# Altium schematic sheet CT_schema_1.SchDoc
size 471 x 471 mm
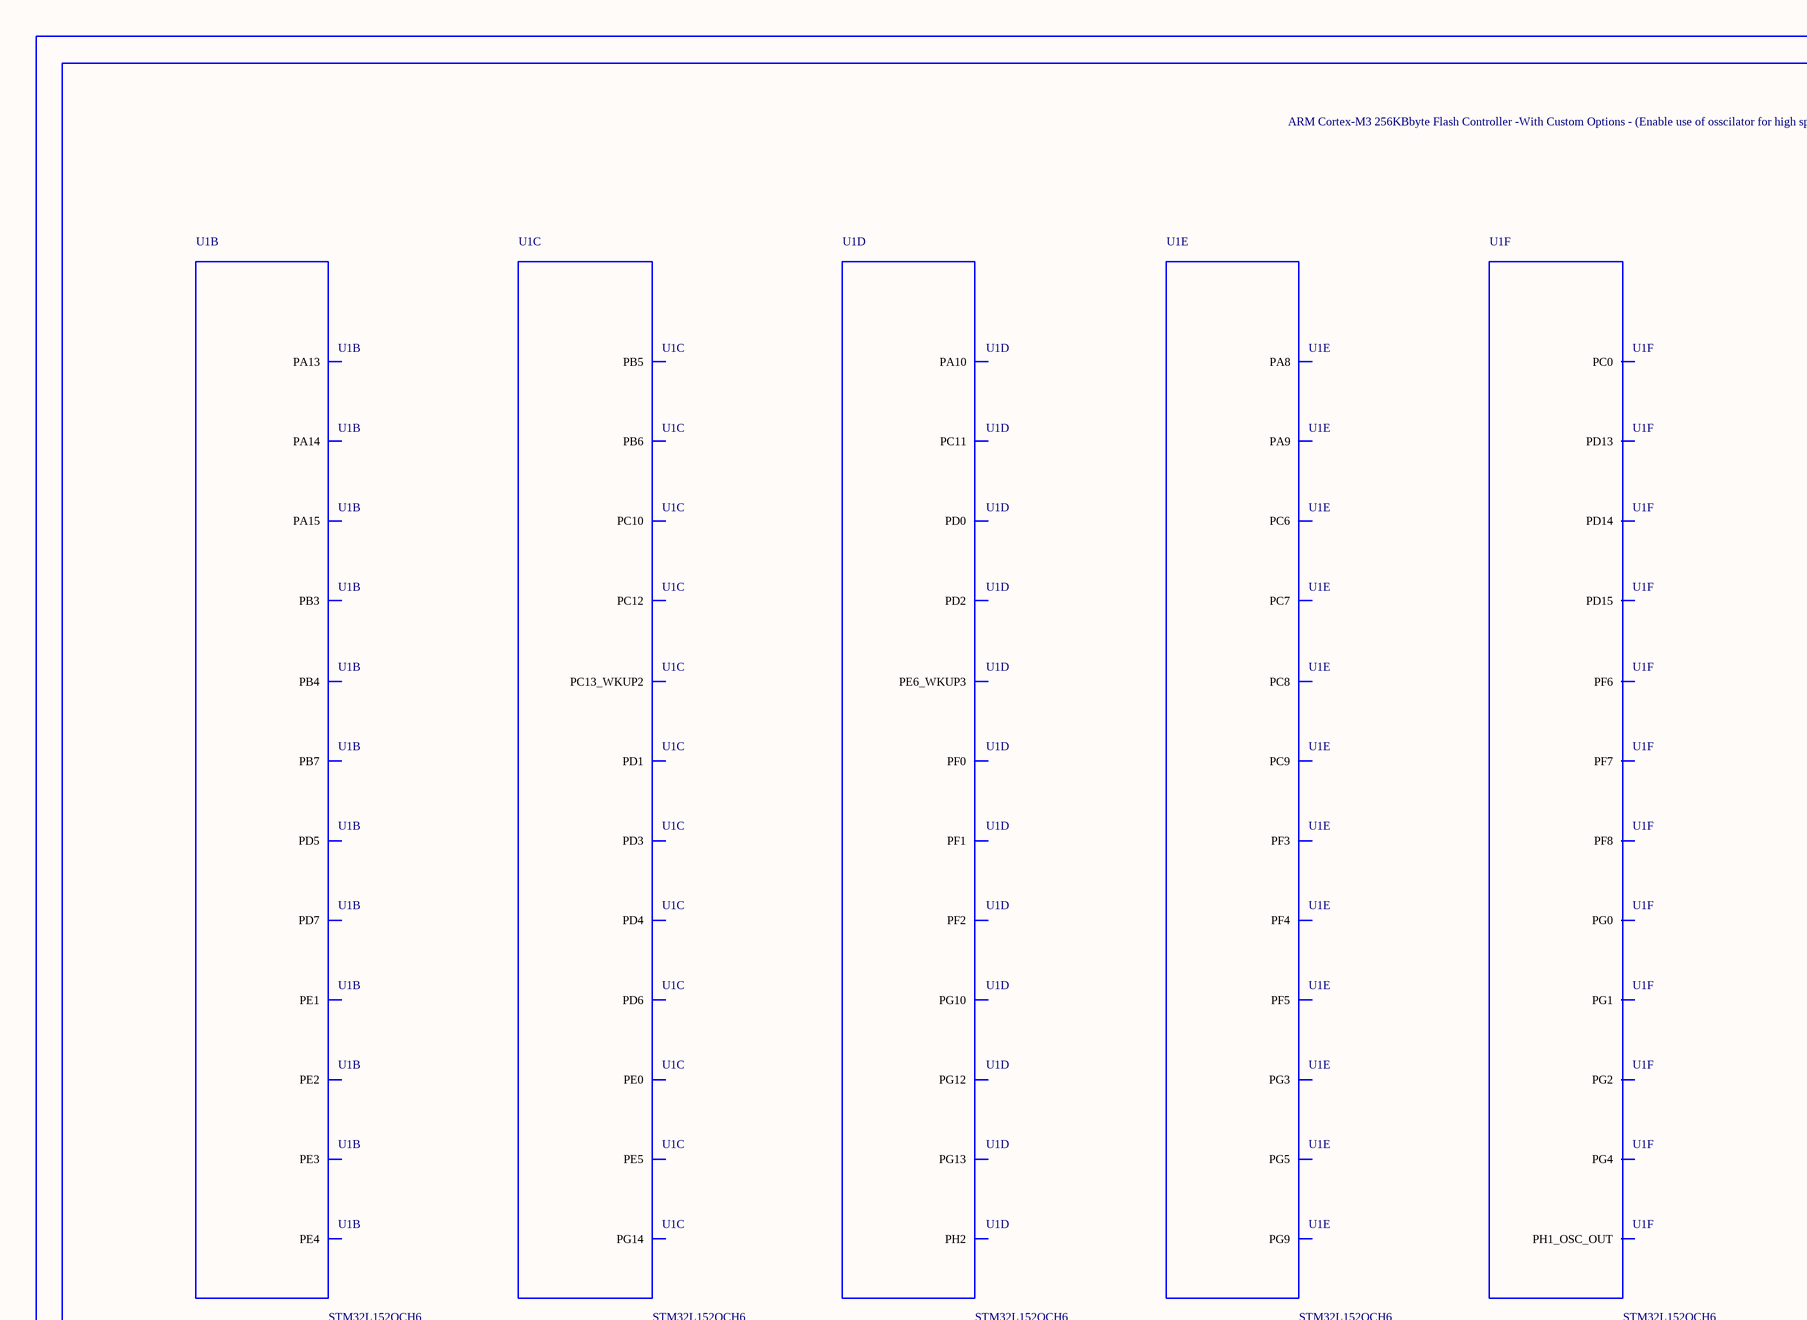
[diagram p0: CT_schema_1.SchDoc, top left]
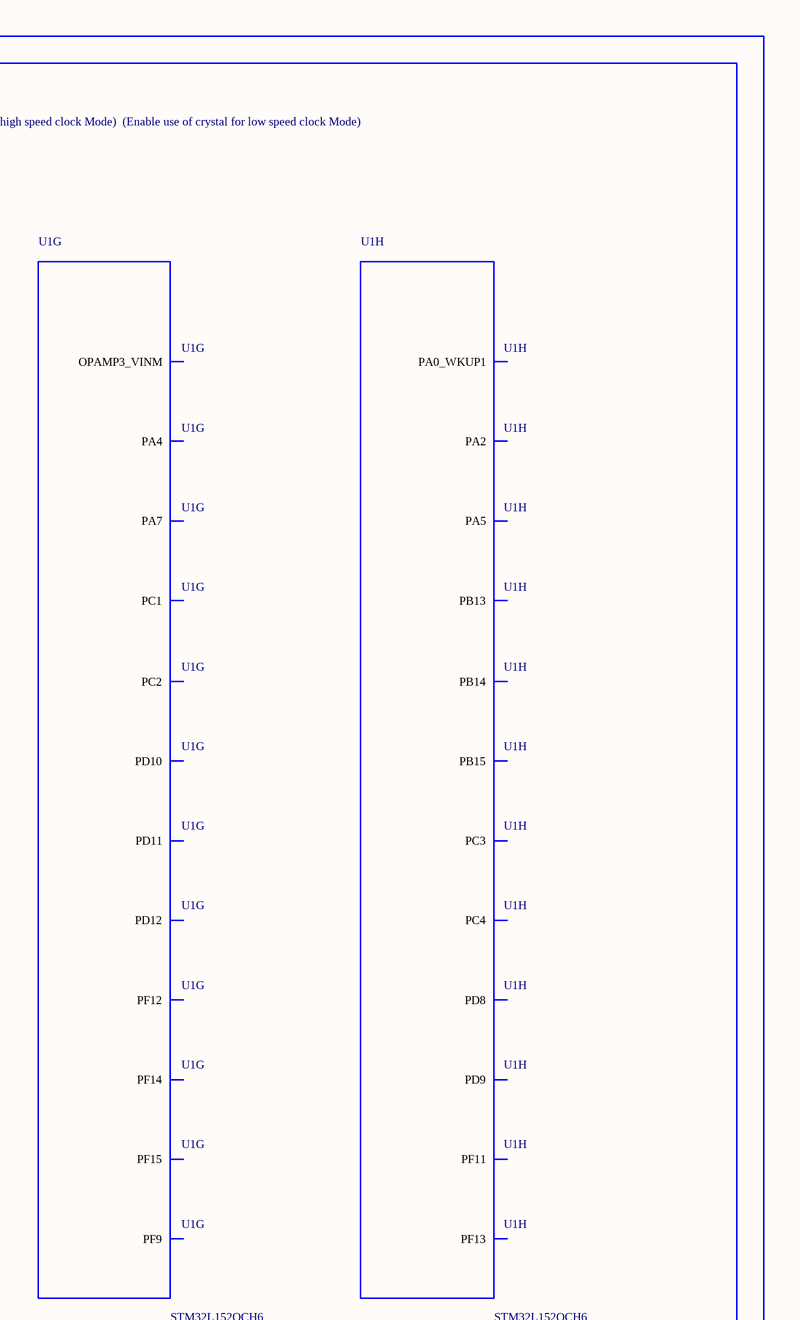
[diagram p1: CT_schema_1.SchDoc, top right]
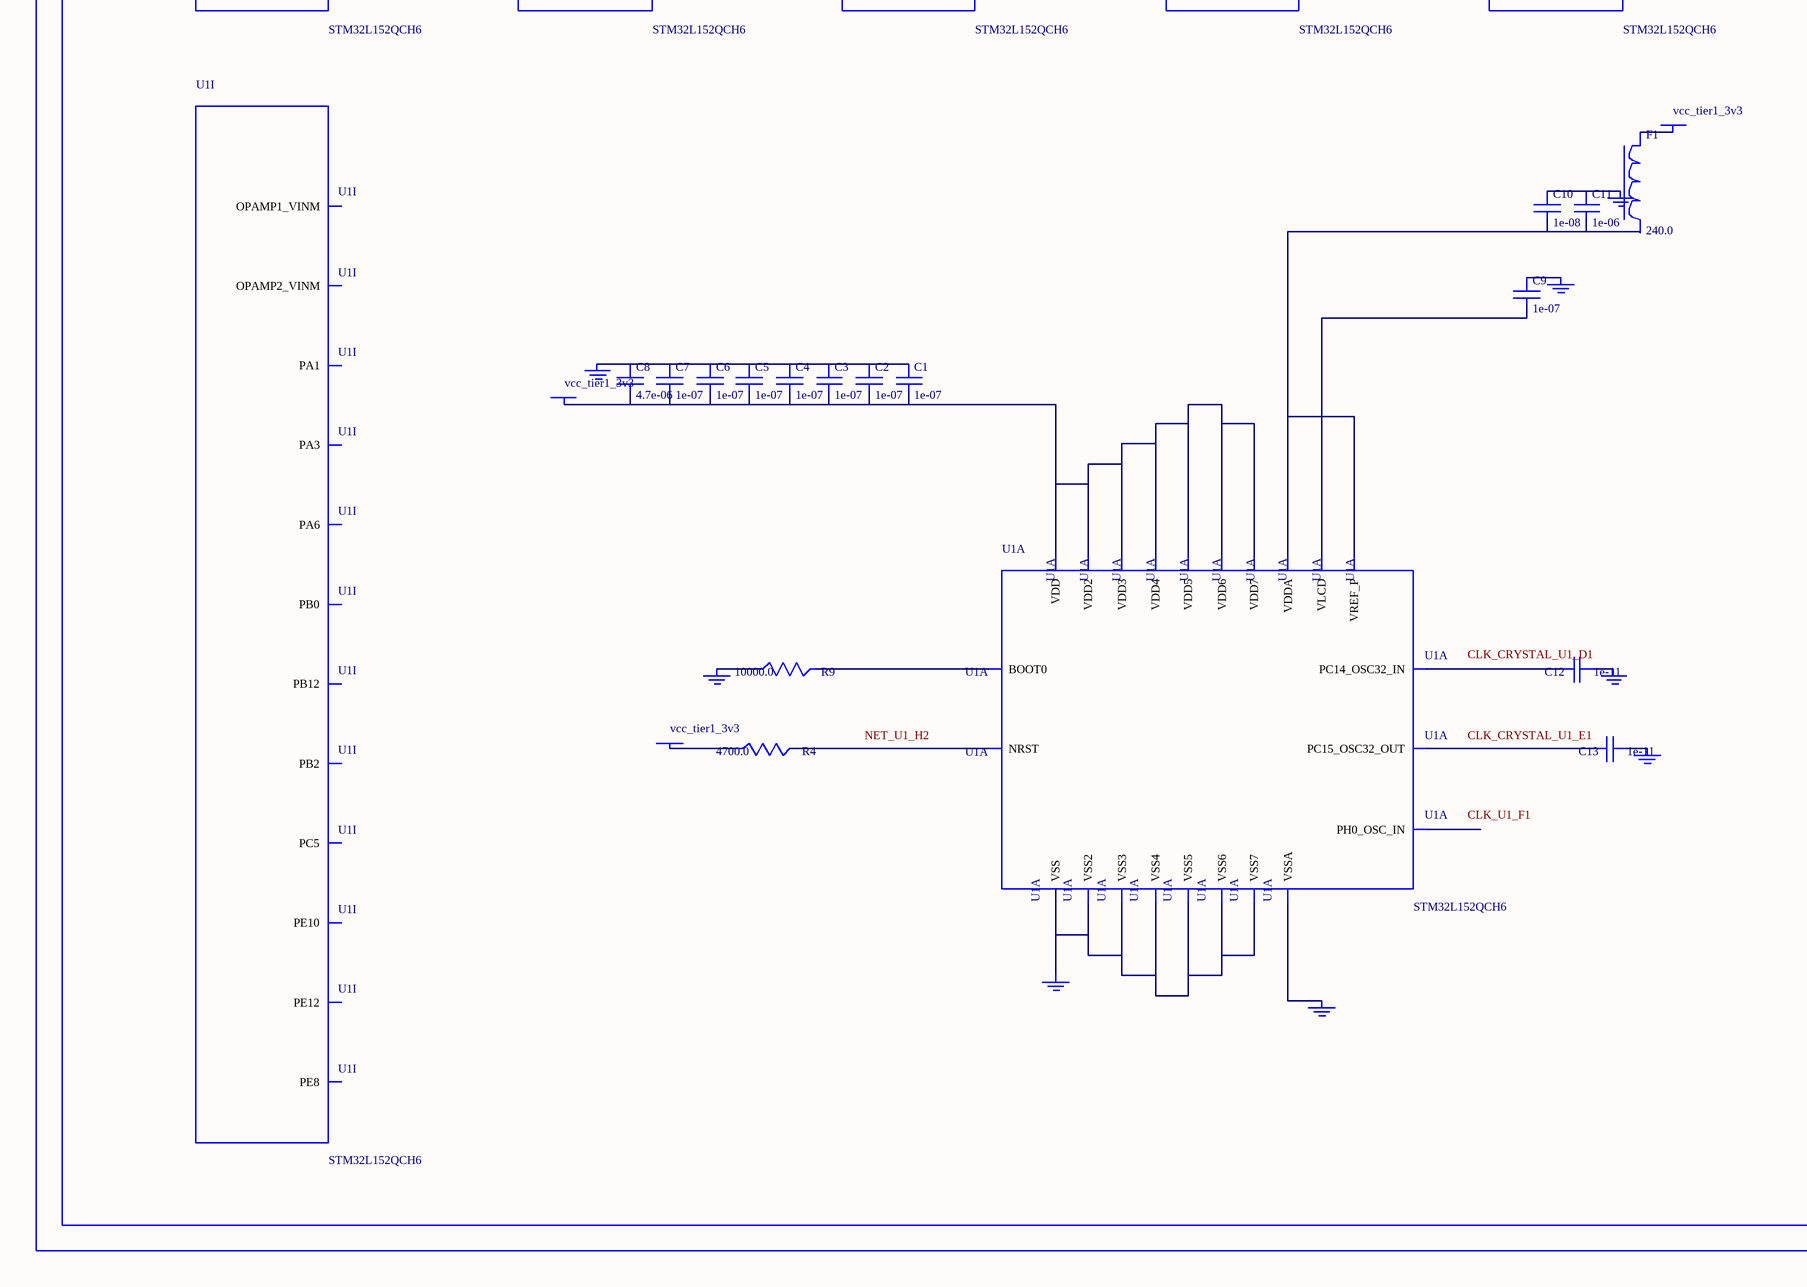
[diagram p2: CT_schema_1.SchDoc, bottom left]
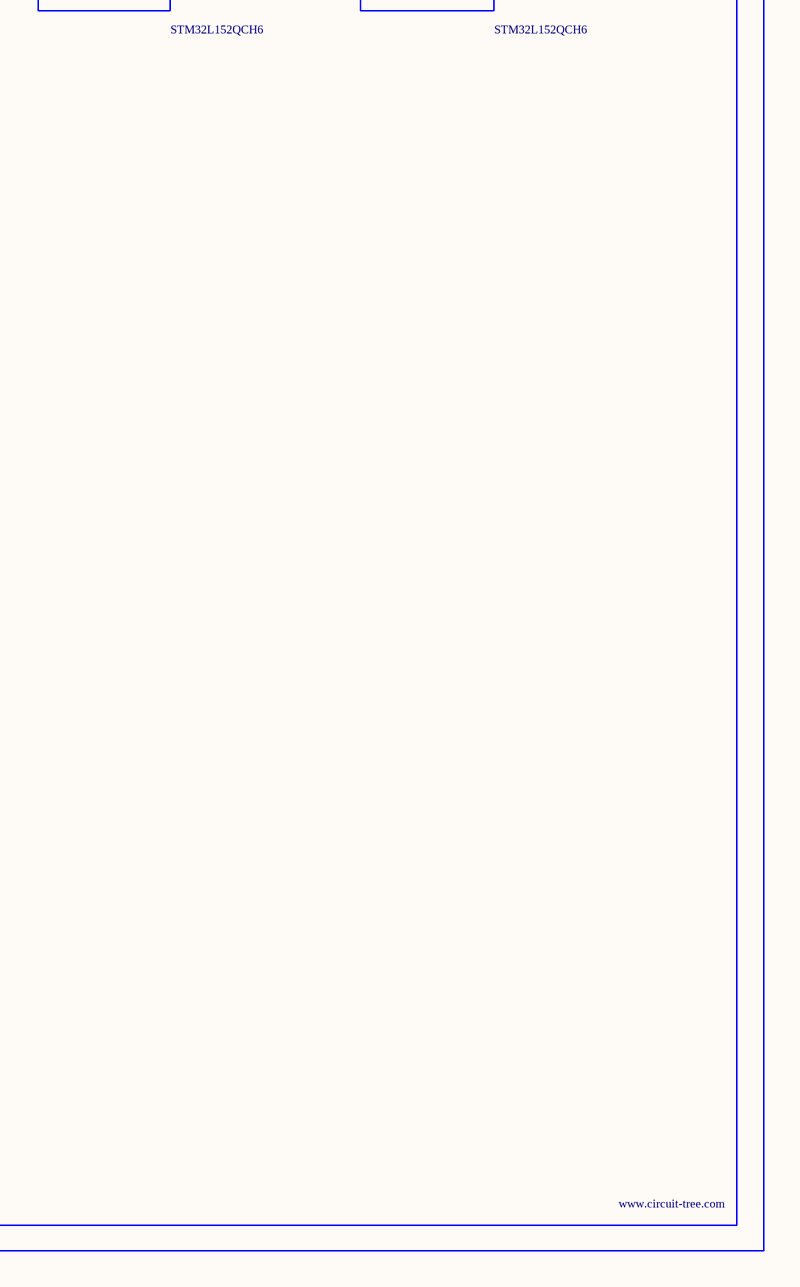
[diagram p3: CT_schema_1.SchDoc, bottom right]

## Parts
BORDER0  (no value)
C1  1e-07  [C0603]
C2  1e-07  [C0603]
C3  1e-07  [C0603]
C4  1e-07  [C0603]
C5  1e-07  [C0603]
C6  1e-07  [C0603]
C7  1e-07  [C0603]
C8  4.7e-06  [C0603]
C9  1e-07  [C0603]
C10  1e-08  [C0603]
C11  1e-06  [C0603]
C12  1e-11  [C0402]
C13  1e-11  [C0402]
F1  240.0  [L0603]
GND_INSTANCE_0_0  (no value)
GND_INSTANCE_0_1  (no value)
GND_INSTANCE_0_2  (no value)
GND_INSTANCE_0_3  (no value)
GND_INSTANCE_0_4  (no value)
GND_INSTANCE_0_5  (no value)
GND_INSTANCE_0_6  (no value)
GND_INSTANCE_0_7  (no value)
POWER_INSTANCE_0_0  vcc_tier1_3v3
POWER_INSTANCE_0_1  vcc_tier1_3v3
POWER_INSTANCE_0_2  vcc_tier1_3v3
R4  4700.0  [R0603]
R9  10000.0  [R0603]
U1  STM32L152QCH6  [UFBGA132]  (parts A,B,C,D,E,F,G,H,I of 12)

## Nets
NetC1_1: C1.1 C2.1 C3.1 C4.1 C5.1 C6.1 C7.1 C8.1 GND_INSTANCE_0_1.0(GND)
NetC1_2: C1.2 C2.2 C3.2 C4.2 C5.2 C6.2 C7.2 C8.2 POWER_INSTANCE_0_1.0(PWR) U1.C4(VDD) U1.G2(VDD4) U1.G6(VDD5) U1.G7(VDD6) U1.G11(VDD2) U1.G12(VDD3) U1.H3(VDD7)
NetC9_1: C9.1 GND_INSTANCE_0_2.0(GND)
NetC9_2: C9.2 U1.E2(VLCD)
NetC10_1: C10.1 C11.1 GND_INSTANCE_0_0.0(GND)
NetC10_2: C10.2 C11.2 U1.L1(VREF_P) U1.M1(VDDA)
NetC12_1: C12.1 GND_INSTANCE_0_4.0(GND)
NetC12_2: C12.2 U1.D1(PC14_OSC32_IN)
NetC13_1: C13.1 GND_INSTANCE_0_5.0(GND)
NetC13_2: C13.2 U1.E1(PC15_OSC32_OUT)
NetF1_1: F1.1 POWER_INSTANCE_0_0.0(PWR)
NetGND_INSTANCE_0_3_0: GND_INSTANCE_0_3.0(GND) R9.1
NetGND_INSTANCE_0_6_0: GND_INSTANCE_0_6.0(GND) U1.J1(VSSA)
NetGND_INSTANCE_0_7_0: GND_INSTANCE_0_7.0(GND) U1.D3(VSS) U1.E3(VSS2) U1.F2(VSS5) U1.F6(VSS6) U1.F7(VSS7) U1.F11(VSS3) U1.F12(VSS4)
NetPOWER_INSTANCE_0_2_0: POWER_INSTANCE_0_2.0(PWR) R4.1
NetR4_2: R4.2 U1.H2(NRST)
NetR9_2: R9.2 U1.A4(BOOT0)

Not connected (* = marked no-connect by the designer): F1 2; U1 A1(PE3) A2(PE1) A5(PD7) A6(PD5) A7(PB4) A8(PB3) A9(PA15) A10(PA14) A11(PA13) B1(PE4) B2(PE2) B4(PB7) B5(PB6) B6(PD6) B7(PD4) B8(PD3) B9(PD1) B10(PC12) B11(PC10) C1(PC13_WKUP2) C2(PE5) C3(PE0) C5(PB5) C6(PG14) C7(PG13) C8(PD2) C9(PD0) C10(PC11) C11(PH2) C12(PA10) D2(PE6_WKUP3) D4(PF2) D5(PF1) D6(PF0) D7(PG12) D8(PG10) D9(PG9) D10(PA9) D11(PA8) D12(PC9) E4(PF3) E9(PG5) E10(PC8) E11(PC7) E12(PC6) F1(PH0_OSC_IN) F3(PF4) F4(PF5) F9(PG3) F10(PG4) G1(PH1_OSC_OUT) G3(PF6) G4(PF7) G9(PG1) G10(PG2) H1(PC0) H4(PF8) H9(PG0) H10(PD15) H11(PD14) H12(PD13) J2(PC1) J3(PC2) J4(PA4) J5(PA7) J6(PF9) J7(PF12) J8(PF14) J9(PF15) J10(PD12) J11(PD11) J12(PD10) K1(OPAMP3_VINM) K2(PC3) K3(PA2) K4(PA5) K5(PC4) K6(PF11) K7(PF13) K8(PD9) K9(PD8) K10(PB15) K11(PB14) K12(PB13) L2(PA0_WKUP1) L3(PA3) L4(PA6) L5(PC5) L6(PB2) L7(PE8) L8(PE10) L9(PE12) L12(PB12) M2(PA1) M3(OPAMP1_VINM) M4(OPAMP2_VINM) M5(PB0)

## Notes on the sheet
- Labels drawn without touching a wire or pin: CLK_CRYSTAL_U1_D1, CLK_CRYSTAL_U1_E1, CLK_U1_F1, NET_U1_H2

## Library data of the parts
BORDER0 = BORDER_PAGE0
C1-C7 C9 = 06035C104K4Z2A
C8 = GRM188R6YA475KE15D
C10 = 06035C103K4Z2A
C11 = C0603C105K3RACTU
C12 C13 = C0402C100K3GACTU
F1 = Z0603C241ASMST
GND_INSTANCE_0_0-GND_INSTANCE_0_7 = GND
POWER_INSTANCE_0_0-POWER_INSTANCE_0_2 = PWR
R4 = RC0603JR-074K7L
R9 = RC0603JR-0710KL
